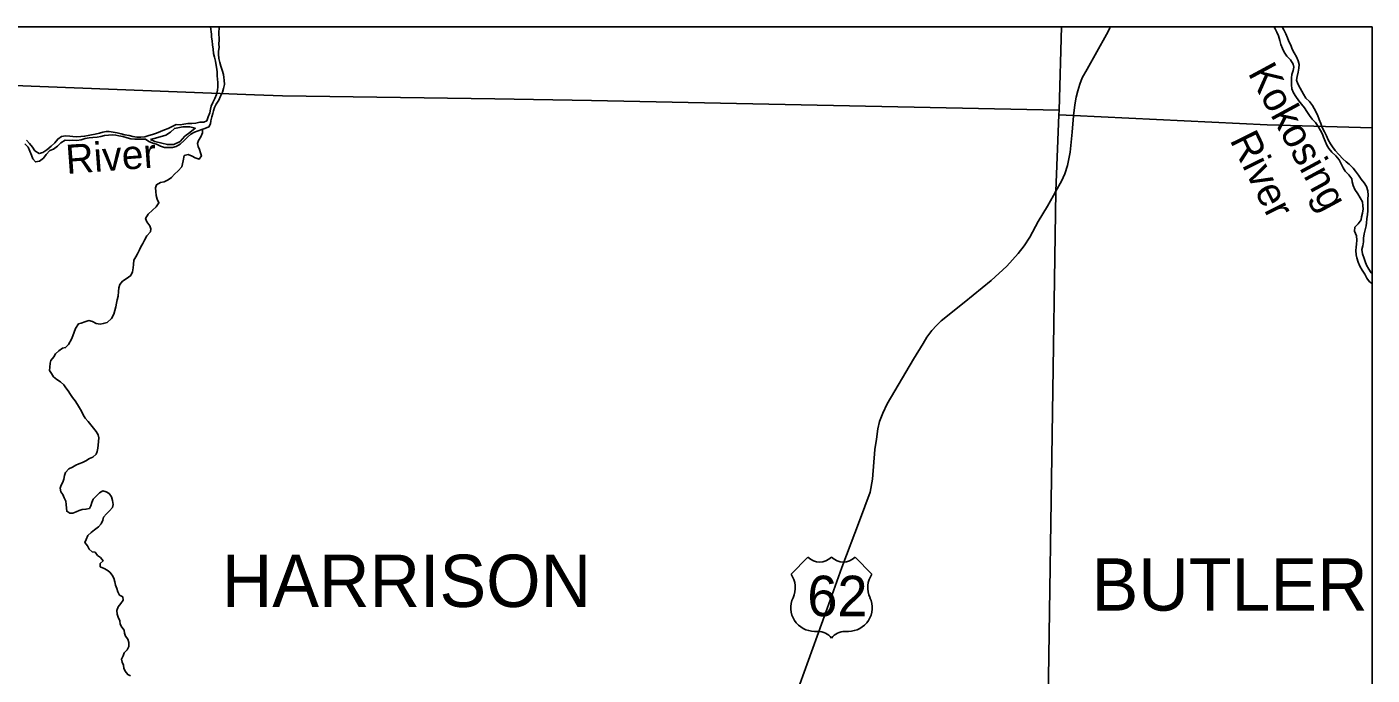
# Model space of a CAD drawing. Extents: x -12.1 to 34, y 0 to 22.
# Drawn here: x 4.28 to 10.44, y 6.6 to 9.57 of the extents above; entities that cross this region are included whole.
import ezdxf

# ---------------------------------------------------------------- set-up
doc = ezdxf.new("R2010")
doc.units = 0
for name, color, linetype in [('GM_X_Major_River', 7, 'Continuous'), ('GM_X_Major_River_Text', 7, 'Continuous'), ('GM_X_Minor_River', 7, 'Continuous'), ('GM_X_Township', 7, 'Continuous'), ('GM_X_Township_Road', 7, 'Continuous'), ('GM_X_Township_Text', 7, 'Continuous'), ('GM_X_US_Location', 7, 'Continuous'), ('GM_X_US_Route', 7, 'Continuous'), ('GM_X_US_Shield', 7, 'Continuous'), ('SH_Text', 7, 'Continuous')]:
    doc.layers.add(name, color=color, linetype=linetype)

msp = doc.modelspace()

# ---------------------------------------------------------------- linework, layer by layer
at = {"layer": 'GM_X_Major_River'}
for points in [[(4.267, 9.0386), (4.2821, 9.0227), (4.2898, 9.0047), (4.2974, 8.9861), (4.3045, 8.9696), (4.3164, 8.9553), (4.3345, 8.9592), (4.353, 8.9728), (4.3651, 8.9894), (4.382, 9.0072), (4.3995, 9.0133), (4.4164, 9.0279), (4.4328, 9.043), (4.4518, 9.0544), (4.47, 9.0535), (4.4875, 9.0548), (4.5057, 9.0539), (4.5248, 9.0567), (4.5434, 9.0623), (4.5615, 9.0657), (4.5796, 9.0675), (4.5993, 9.0693), (4.6163, 9.0726), (4.6328, 9.0765), (4.6504, 9.0778), (4.6674, 9.079), (4.6845, 9.0776), (4.6978, 9.0756), (4.7171, 9.0721), (4.7358, 9.0653), (4.7534, 9.0613), (4.7721, 9.0604), (4.7897, 9.06), (4.8067, 9.0597), (4.8201, 9.0593), (4.8356, 9.0488), (4.8538, 9.042), (4.8709, 9.0369), (4.8897, 9.0269), (4.9068, 9.0212), (4.9249, 9.0209), (4.9436, 9.0211), (4.9611, 9.0266), (4.9786, 9.0374), (4.9965, 9.052), (5.0124, 9.0682), (5.0277, 9.0828), (5.0446, 9.0915), (5.0611, 9.0981), (5.0786, 9.1041), (5.0924, 9.108), (5.111, 9.1162), (5.1173, 9.1296), (5.1193, 9.144), (5.1239, 9.1622), (5.128, 9.1767), (5.131, 9.19), (5.1357, 9.2045), (5.1441, 9.2201), (5.1561, 9.2378), (5.1645, 9.256), (5.1723, 9.2743), (5.178, 9.2925), (5.1815, 9.3106), (5.1802, 9.3293), (5.179, 9.3426), (5.1768, 9.3565), (5.1707, 9.3756), (5.1657, 9.3943), (5.1607, 9.4113), (5.1563, 9.4299), (5.1545, 9.4491), (5.1554, 9.4625), (5.1574, 9.4796), (5.1561, 9.4961), (5.157, 9.5137), (5.1567, 9.55), (5.157, 9.5682), (5.1566, 9.5741)], [(5.1179, 9.5741), (5.1221, 9.5411), (5.1222, 9.5272), (5.1251, 9.5107), (5.1279, 9.4921), (5.1297, 9.4718), (5.1315, 9.4526), (5.1365, 9.4356), (5.1415, 9.4164), (5.1438, 9.3972), (5.1472, 9.3797), (5.1489, 9.3663), (5.1491, 9.3487), (5.1503, 9.3354), (5.1516, 9.3178), (5.1523, 9.2991), (5.1503, 9.2847), (5.1457, 9.2638), (5.1379, 9.2461), (5.128, 9.2284), (5.1218, 9.2113), (5.1182, 9.1968), (5.1146, 9.1797), (5.1068, 9.1615), (5.1006, 9.1444), (5.0868, 9.1378), (5.0692, 9.1371), (5.0501, 9.1332), (5.032, 9.1314), (5.0144, 9.1312), (4.9958, 9.1278), (4.9787, 9.126), (4.9601, 9.1274), (4.942, 9.1182), (4.9246, 9.1079), (4.907, 9.1018), (4.889, 9.0952), (4.8699, 9.0875), (4.8518, 9.0815), (4.8353, 9.076), (4.8167, 9.071), (4.7981, 9.0692), (4.7811, 9.0685), (4.7624, 9.0725), (4.7447, 9.0761), (4.726, 9.0796), (4.7089, 9.0848), (4.6908, 9.0884), (4.6534, 9.0954), (4.6396, 9.0948), (4.6252, 9.0919), (4.6093, 9.087), (4.5901, 9.083), (4.5731, 9.0802), (4.5571, 9.0758), (4.5412, 9.0729), (4.5241, 9.0717), (4.506, 9.0704), (4.4879, 9.0718), (4.473, 9.0727), (4.4538, 9.0747), (4.4351, 9.0724), (4.4182, 9.0604), (4.4045, 9.0422), (4.3876, 9.027), (4.3675, 9.0103), (4.3495, 8.9984), (4.3325, 8.9939), (4.3127, 9.0065), (4.3024, 9.023), (4.2889, 9.0394), (4.2749, 9.0552)], [(9.9899, 9.5741), (9.9931, 9.5679), (10.0034, 9.5504), (10.0105, 9.5333), (10.0166, 9.5121), (10.0211, 9.4934), (10.0293, 9.4754), (10.0364, 9.4578), (10.0483, 9.4403), (10.065, 9.4229), (10.078, 9.4033), (10.0802, 9.39), (10.0782, 9.375), (10.0721, 9.3557), (10.0701, 9.3413)], [(10.0725, 9.4726), (10.0664, 9.4902), (10.0572, 9.5077), (10.0511, 9.5242), (10.0435, 9.5428), (10.0353, 9.5603), (10.0278, 9.5741)], [(10.4394, 8.4424), (10.4358, 8.4469), (10.4244, 8.4644), (10.413, 8.483), (10.4075, 8.4995), (10.4026, 8.5133), (10.3955, 8.534), (10.3931, 8.5538), (10.3967, 8.5709), (10.4002, 8.5896), (10.4006, 8.6061), (10.4025, 8.6259), (10.4071, 8.6441), (10.4117, 8.6623), (10.4137, 8.6767), (10.4157, 8.6949), (10.4176, 8.7141), (10.4196, 8.7307), (10.4199, 8.7515), (10.4202, 8.7696), (10.4206, 8.7856), (10.421, 8.8027), (10.4191, 8.823), (10.4136, 8.8421), (10.4028, 8.8591), (10.3898, 8.8771), (10.3774, 8.8951), (10.3633, 8.9126), (10.3525, 8.9269), (10.3347, 8.9454), (10.3213, 8.9565), (10.3052, 8.9702), (10.2874, 8.9887), (10.2707, 9.0072), (10.2577, 9.0252), (10.2485, 9.039), (10.2387, 9.0559), (10.2306, 9.0745), (10.2208, 9.0936), (10.211, 9.1138), (10.2039, 9.1314), (10.1967, 9.1505), (10.1891, 9.1718), (10.1738, 9.2004), (10.1662, 9.2142), (10.1533, 9.2317), (10.1361, 9.2475), (10.1247, 9.2656), (10.1171, 9.2794), (10.1095, 9.2937), (10.0986, 9.3128), (10.0931, 9.3298), (10.0967, 9.3469), (10.1007, 9.3662), (10.1037, 9.3854), (10.1052, 9.402), (10.1007, 9.4179), (10.0925, 9.4371), (10.0817, 9.4546), (10.0725, 9.4726)], [(10.0701, 9.3413), (10.0702, 9.328), (10.0699, 9.3088), (10.0722, 9.2906), (10.0793, 9.272), (10.0896, 9.2551), (10.1031, 9.236), (10.1155, 9.2206), (10.1301, 9.2032), (10.1404, 9.1857), (10.1523, 9.1676), (10.1653, 9.1518), (10.1804, 9.1354), (10.1928, 9.1184), (10.2037, 9.0999), (10.2124, 9.0829), (10.2173, 9.0685), (10.2249, 9.0505), (10.2321, 9.0329), (10.2407, 9.017), (10.2548, 8.9995), (10.2731, 8.9826), (10.2892, 8.9647), (10.298, 8.9466), (10.3061, 8.928), (10.3164, 8.9137), (10.3321, 8.8957), (10.3461, 8.8777), (10.3478, 8.8644), (10.3523, 8.8468), (10.361, 8.8293), (10.3734, 8.8097), (10.3848, 8.7912), (10.3957, 8.7726), (10.3975, 8.7539), (10.3987, 8.7406), (10.3957, 8.7213), (10.3916, 8.7037), (10.3891, 8.6898), (10.3759, 8.671), (10.3606, 8.6559), (10.3587, 8.6377), (10.368, 8.6165), (10.3698, 8.5973), (10.3673, 8.5791), (10.3658, 8.5641), (10.3655, 8.5497), (10.3667, 8.53), (10.3701, 8.5162), (10.3751, 8.4954), (10.3838, 8.4779), (10.3946, 8.4588), (10.406, 8.4418), (10.4158, 8.4232), (10.4282, 8.4058), (10.4394, 8.3988)], [(5.0228, 9.0907), (5.0482, 9.1097), (5.0231, 9.1163), (4.9911, 9.1155), (4.9528, 9.1092), (4.9343, 9.0925), (4.9137, 9.0784), (4.877, 9.0679), (4.8435, 9.0579)], [(4.8435, 9.0579), (4.8633, 9.0485), (4.8943, 9.0419), (4.9205, 9.0347), (4.9498, 9.035), (4.979, 9.0486), (5.0006, 9.0734), (5.0228, 9.0907)]]:
    msp.add_lwpolyline(points, dxfattribs=at)
at = {"layer": 'GM_X_Minor_River'}
for points in [[(5.081, 9.1048), (5.0814, 9.088), (5.074, 9.0703), (5.0623, 9.0532), (5.0586, 9.0398), (5.0613, 9.0265), (5.0678, 9.0121), (5.0727, 8.9977), (5.0764, 8.9839), (5.0664, 8.9683), (5.0477, 8.9741), (5.0338, 8.9821), (5.0161, 8.9901), (4.998, 8.9841), (4.9922, 8.9611), (4.9902, 8.9473), (4.9865, 8.9323), (4.97, 8.9146), (4.953, 8.8986), (4.9387, 8.8846), (4.9238, 8.8734), (4.9062, 8.8648), (4.8892, 8.861), (4.8711, 8.8508), (4.8663, 8.8364), (4.8674, 8.8198), (4.8691, 8.8022), (4.874, 8.7846), (4.8815, 8.7676), (4.8698, 8.7494), (4.8528, 8.7344), (4.8332, 8.7167), (4.8204, 8.6964), (4.8264, 8.6809), (4.8403, 8.6628), (4.8441, 8.6484), (4.8425, 8.635), (4.8271, 8.6168), (4.815, 8.5965), (4.8081, 8.5816), (4.7996, 8.566), (4.7933, 8.5527), (4.7837, 8.5345), (4.7758, 8.5206), (4.7673, 8.5046), (4.7658, 8.4859), (4.7642, 8.4698), (4.76, 8.4517), (4.7526, 8.4351), (4.7324, 8.4196), (4.7154, 8.4088), (4.7021, 8.3944), (4.6974, 8.3789), (4.6958, 8.3618), (4.6943, 8.341), (4.6907, 8.3234), (4.6875, 8.3089), (4.6838, 8.2908), (4.6796, 8.2753), (4.6744, 8.2576), (4.6638, 8.2373), (4.6446, 8.2191), (4.6265, 8.2148), (4.6127, 8.2126), (4.5945, 8.2147), (4.5769, 8.2237), (4.5609, 8.2284), (4.5427, 8.223), (4.5262, 8.2171), (4.5129, 8.2128), (4.4991, 8.1919), (4.4939, 8.1754), (4.4875, 8.1583), (4.4812, 8.1428)], [(4.4812, 8.1428), (4.4672, 8.1193), (4.4539, 8.1049), (4.44, 8.1016), (4.4235, 8.0904), (4.4075, 8.0754), (4.4001, 8.0621), (4.3873, 8.0461), (4.3836, 8.0327), (4.3821, 8.0145), (4.381, 8.0001), (4.3896, 7.9852), (4.3992, 7.9707), (4.4136, 7.9585), (4.4312, 7.9478), (4.4467, 7.9345), (4.4558, 7.9206), (4.4659, 7.9067), (4.4771, 7.8896), (4.4851, 7.8757), (4.4985, 7.8603), (4.5081, 7.8437), (4.5177, 7.8282), (4.5263, 7.8128), (4.5354, 7.7967), (4.5434, 7.7813), (4.5573, 7.7663), (4.5701, 7.7508), (4.5824, 7.7359), (4.5941, 7.7204), (4.6032, 7.7044), (4.607, 7.6905), (4.6054, 7.675), (4.6038, 7.6579), (4.6022, 7.6435), (4.5991, 7.6291), (4.5948, 7.6157), (4.5794, 7.6024), (4.5639, 7.597), (4.5464, 7.5852), (4.5314, 7.5783), (4.5155, 7.5713), (4.5005, 7.5665), (4.4856, 7.5569), (4.4697, 7.5483), (4.4532, 7.5317), (4.4489, 7.5184), (4.4457, 7.5024), (4.442, 7.4879), (4.4341, 7.4746), (4.4293, 7.4612), (4.433, 7.4441), (4.4416, 7.4308), (4.4475, 7.4158), (4.4555, 7.4009), (4.4571, 7.3859), (4.4577, 7.3694), (4.4593, 7.3544), (4.4737, 7.3453), (4.487, 7.3454), (4.5019, 7.3523), (4.5169, 7.3587), (4.5307, 7.363), (4.5472, 7.3636), (4.5632, 7.3668), (4.5696, 7.3801), (4.5749, 7.3946), (4.5802, 7.4106), (4.594, 7.4245), (4.61, 7.4384), (4.6249, 7.448), (4.6393, 7.4438), (4.6537, 7.4358), (4.6649, 7.4203), (4.6692, 7.4032), (4.6725, 7.3861), (4.6687, 7.3717), (4.656, 7.3562), (4.6411, 7.3428), (4.6278, 7.3273), (4.6246, 7.314), (4.6177, 7.2963), (4.6055, 7.283), (4.5873, 7.2701), (4.5719, 7.2568), (4.5559, 7.2434), (4.5485, 7.2258), (4.5427, 7.2113), (4.5544, 7.1959), (4.5619, 7.1809), (4.5752, 7.1692), (4.5891, 7.1665), (4.6009, 7.1521), (4.6147, 7.142), (4.6259, 7.1281), (4.6121, 7.1147), (4.6132, 7.1003), (4.6303, 7.0923), (4.6441, 7.0854), (4.6575, 7.0752), (4.6676, 7.0614)], [(4.6676, 7.0614), (4.6746, 7.0475), (4.6805, 7.0309), (4.6832, 7.0154), (4.689, 7), (4.6928, 6.9861), (4.7013, 6.9706), (4.7158, 6.9621), (4.7179, 6.9466), (4.7067, 6.9316), (4.6945, 6.9161), (4.6892, 6.8995), (4.6903, 6.883), (4.6956, 6.8691), (4.7021, 6.8531), (4.7037, 6.8376), (4.7112, 6.8232), (4.7218, 6.8098), (4.724, 6.7965), (4.7288, 6.7821), (4.74, 6.7682), (4.7443, 6.7527), (4.7443, 6.7356), (4.7364, 6.7196), (4.7231, 6.7062), (4.7178, 6.6928), (4.7098, 6.6768), (4.7141, 6.6624), (4.72, 6.649), (4.7216, 6.6352), (4.7275, 6.6213), (4.7387, 6.6063), (4.752, 6.5999)]]:
    msp.add_lwpolyline(points, dxfattribs=at)
at = {"layer": 'GM_X_Township'}
for points in [[(9.0158, 9.5741), (9.0053, 9.1925), (9.0041, 9.1707), (9.0711, 9.1675), (9.9585, 9.1256), (10.4394, 9.1109)], [(3.2217, 9.3449), (3.4445, 9.3346), (3.6655, 9.3268), (3.6954, 9.3252), (3.7051, 9.3248), (5.3194, 9.2629), (5.4483, 9.2584), (6.4204, 9.2438), (6.8632, 9.2368), (9.0053, 9.1925), (9.0041, 9.1707)], [(8.8923, 2.1565), (8.8936, 2.2148), (8.9101, 3.5189), (8.913, 3.7042), (8.9183, 3.9633), (8.9176, 4.0271), (8.9142, 4.0522), (8.9156, 4.0653), (8.9204, 4.0765), (8.9335, 5.0704), (8.9403, 5.4765), (8.991, 8.8216), (9.0041, 9.1707)]]:
    msp.add_lwpolyline(points, dxfattribs=at)
at = {"layer": 'GM_X_Township_Road'}
msp.add_lwpolyline([(8.9524, 8.7527), (8.9797, 8.8008), (8.9913, 8.8208)], dxfattribs=at)
at = {"layer": 'GM_X_US_Route'}
for points in [[(8.9913, 8.8208), (9.0161, 8.8667), (9.0313, 8.9011), (9.0446, 8.9387), (9.0566, 8.9995), (9.0656, 9.0923), (9.0714, 9.1667), (9.0782, 9.2172), (9.0841, 9.2527), (9.0909, 9.2817), (9.1003, 9.3123), (9.1116, 9.3413), (9.1337, 9.3804), (9.2226, 9.539), (9.2376, 9.5678), (9.2396, 9.5741)], [(8.9524, 8.7527), (8.9797, 8.8008), (8.9913, 8.8208)], [(7.7785, 6.4524), (7.9568, 6.9465), (8.0101, 7.0971), (8.0916, 7.3108), (8.1394, 7.4425), (8.1503, 7.5018), (8.1619, 7.6378), (8.1686, 7.6853), (8.1754, 7.733), (8.1829, 7.7663), (8.198, 7.8037), (8.2179, 7.8471), (8.3389, 8.0523), (8.3821, 8.1241), (8.4002, 8.153), (8.423, 8.1826), (8.4444, 8.2058), (8.4656, 8.2267), (8.5699, 8.3113), (8.694, 8.4119), (8.7656, 8.4783), (8.8176, 8.5361), (8.8451, 8.5705), (8.8714, 8.6111), (8.9103, 8.6821), (8.9524, 8.7527)]]:
    msp.add_lwpolyline(points, dxfattribs=at)
at = {"layer": 'GM_X_US_Shield'}
for p, q in [((7.8547, 7.1441), (7.7775, 7.0669)), ((8.1483, 7.0669), (8.071, 7.1441)), ((7.8856, 6.8042), (7.9011, 6.8042)), ((8.0247, 6.8042), (8.0401, 6.8042))]:
    msp.add_line(p, q, dxfattribs=at)
for centre, radius, start, end in [((7.9088, 7.1993), 0.0772, 225.573, 314.427), ((8.017, 7.1993), 0.0772, 225.573, 314.427), ((7.6889, 7.0048), 0.1081, 334.54712, 35.00093), ((8.2369, 7.0048), 0.1081, 144.99907, 205.45288), ((7.8844, 6.9124), 0.1081, 154.83192, 270.63826), ((8.0413, 6.9124), 0.1081, 269.36174, 25.16808), ((7.9011, 6.727), 0.0772, 36.8699, 90), ((8.0247, 6.727), 0.0772, 90, 143.1301)]:
    msp.add_arc(centre, radius, start, end, dxfattribs=at)
at = {"layer": 'SH_Text'}
msp.add_lwpolyline([(3.2217, 9.5741), (10.4394, 9.5741), (10.4394, 2.1565), (3.2217, 2.1565)], close=True, dxfattribs=at)

# ---------------------------------------------------------------- texts
at = {"layer": 'GM_X_Major_River_Text'}
for s, rotation, p in [('Kokosing', 298.42654, (9.8685, 9.3631)), ('River', 296.2119, (9.7854, 9.0559)), ('River', 4.2126, (4.4593, 8.9001))]:
    msp.add_text(s, height=0.13318, rotation=rotation, dxfattribs=at).set_placement(p)
at = {"layer": 'GM_X_Township_Text'}
for s, p in [('HARRISON', (5.1697, 6.9161)), ('BUTLER', (9.1545, 6.8992))]:
    msp.add_text(s, height=0.2397, rotation=0.00001, dxfattribs=at).set_placement(p)
at = {"layer": 'GM_X_US_Location'}
for s in ['0', '/']:
    msp.add_text(s, height=0.000266, dxfattribs=at).set_placement((7.9628, 6.965))
msp.add_text('62', height=0.000266, rotation=0.00001, dxfattribs=at).set_placement((7.9078, 6.9099))
at = {"layer": 'GM_X_US_Shield'}
msp.add_text('62', height=0.18539, dxfattribs=at).set_placement((7.8521, 6.8738))

doc.saveas('drawing.dxf')
